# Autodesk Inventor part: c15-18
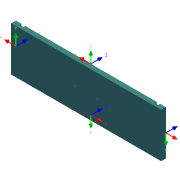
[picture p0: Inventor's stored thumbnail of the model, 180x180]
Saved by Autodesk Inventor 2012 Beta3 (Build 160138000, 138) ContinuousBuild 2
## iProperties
Created: 2011-02
Part Number: c15-18
Material: Default
Document SubType Name: Modeling
Designer: Beta-8540w
Density: 1 g/cm^3
Author: Beta-8540w
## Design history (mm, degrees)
sketch "Sketch1"
  geometry: L1 (-254, -75.2)-(254, -75.2); L2 (254, -75.2)-(254, 75.2); L3 (254, 75.2)-(-254, 75.2); L4 (-254, 75.2)-(-254, -75.2); 3 further points
  constraints: 8 end point, 2 midpoint, 2 parallel, 1 horizontal, 1 horizontal alignment, 1 perpendicular, 1 vertical alignment
  dimensions: "drawer_core_width" = 508 distance of L3.end L2.end; "drawer_core_height" = 150.4 distance of L2.end L1.end (= drawer_height - 2 x edge_band_thickness)
extrude "Drawer Face" new body sketch "Sketch1" distance "d2" = 15.875; taper "d3" = 0 deg
sketch "Sketch2"
  geometry: 1 further point
hole "Single Hole Pull" sketch "Sketch2" at (0, 0) diameter "d4" = 4.4958; stored, may be unused: countersink angle "d8" = 82 deg, drill point angle "d10" = 118 deg; dims "d5" = 19.05, "d6" = 8.4328, "d7" = 6.35, "d9" = 25.4
sketch "Sketch3"
  geometry: L1 (-38.1, 0)-(38.1, 0); 2 further points
  constraints: 2 end point, 1 coincident, 1 horizontal, 1 midpoint
  dimensions: "pull_width" = 76.2 distance of L1.start L1.end
hole "Double Hole Pull" sketch "Sketch3" at (-38.1, 0), (38.1, 0) diameter "d12" = 4.4958; stored, may be unused: countersink angle "d16" = 82 deg, drill point angle "d18" = 118 deg; dims "d13" = 19.05, "d14" = 8.4328, "d15" = 6.35, "d17" = 25.4
sketch "Sketch4"
  geometry: L1 (254, -75.2)-(-254, -75.2) reference; L2 (254, 75.2)-(254, -75.2) reference; L3 (-254, 75.2)-(254, 75.2) reference; L4 (-254, -75.2)-(-254, 75.2) reference; L5 (-234.95, 75.2)-(-222.25, 75.2); L6 (-222.25, 75.2)-(-222.25, -75.2); L7 (-222.25, -75.2)-(-234.95, -75.2); L8 (-234.95, -75.2)-(-234.95, 75.2); L9 (234.95, 75.2)-(222.25, 75.2); L10 (222.25, 75.2)-(222.25, -75.2); L11 (222.25, -75.2)-(234.95, -75.2); L12 (234.95, -75.2)-(234.95, 75.2); 1 further point
  constraints: 16 end point, 4 parallel, 4 point on line, 2 horizontal, 2 perpendicular, 1 collinear
  dimensions: "d19" = 12.7 distance of L5.start L5.end; "d20" = 19.05 distance between parallel lines of L8 L4; "d21" = 19.05 distance between parallel lines of L2 L12 (= d20)
extrude "Side Relief" cut sketch "Sketch4" distance "d22" = 6.35; taper "d23" = 0 deg
sketch "Sketch5"
  geometry: L1 (222.25, -75.2)-(222.25, 75.2) reference; L2 (-222.25, 75.2)-(-222.25, -75.2) reference; L3 (222.25, -75.2)-(-222.25, -75.2) reference; L4 (-222.25, -65.548)-(222.25, -65.548); L5 (222.25, -65.548)-(222.25, -62.246); L6 (222.25, -62.246)-(-222.25, -62.246); L7 (-222.25, -62.246)-(-222.25, -65.548); 1 further point
  constraints: 8 end point, 2 parallel, 2 point on line, 1 horizontal, 1 perpendicular
  dimensions: "d24" = 9.652 distance between parallel lines of L3 L4; "d25" = 3.302 distance of L4.end L5.end
extrude "Bottom Relief" cut sketch "Sketch5" distance "d26" = 6.35; taper "d27" = 0 deg
body "Solid1"
other parameters: "d28" = 0, "d29" = 0, "d30" = 0, "d31" = 0, "d32" = 0, "d33" = 180 deg, "d40" = 0, "d41" = 0, "d42" = 0, "d43" = 0, "d44" = 180 deg, "d45" = 180 deg, "d46" = 0, "d47" = 0, "d48" = 0, "d49" = 0, "d50" = 180 deg, "d51" = 0, "d52" = 0, "d53" = 0, "d54" = 0, "d55" = 0, "d56" = 180 deg, "d57" = 0, "drawer_width" = 406.4 [user parameter], "edge_band_thickness" = 1 [user parameter; used in 1 equation term], "drawer_height" = 152.4 [user parameter; used in 1 equation term]
